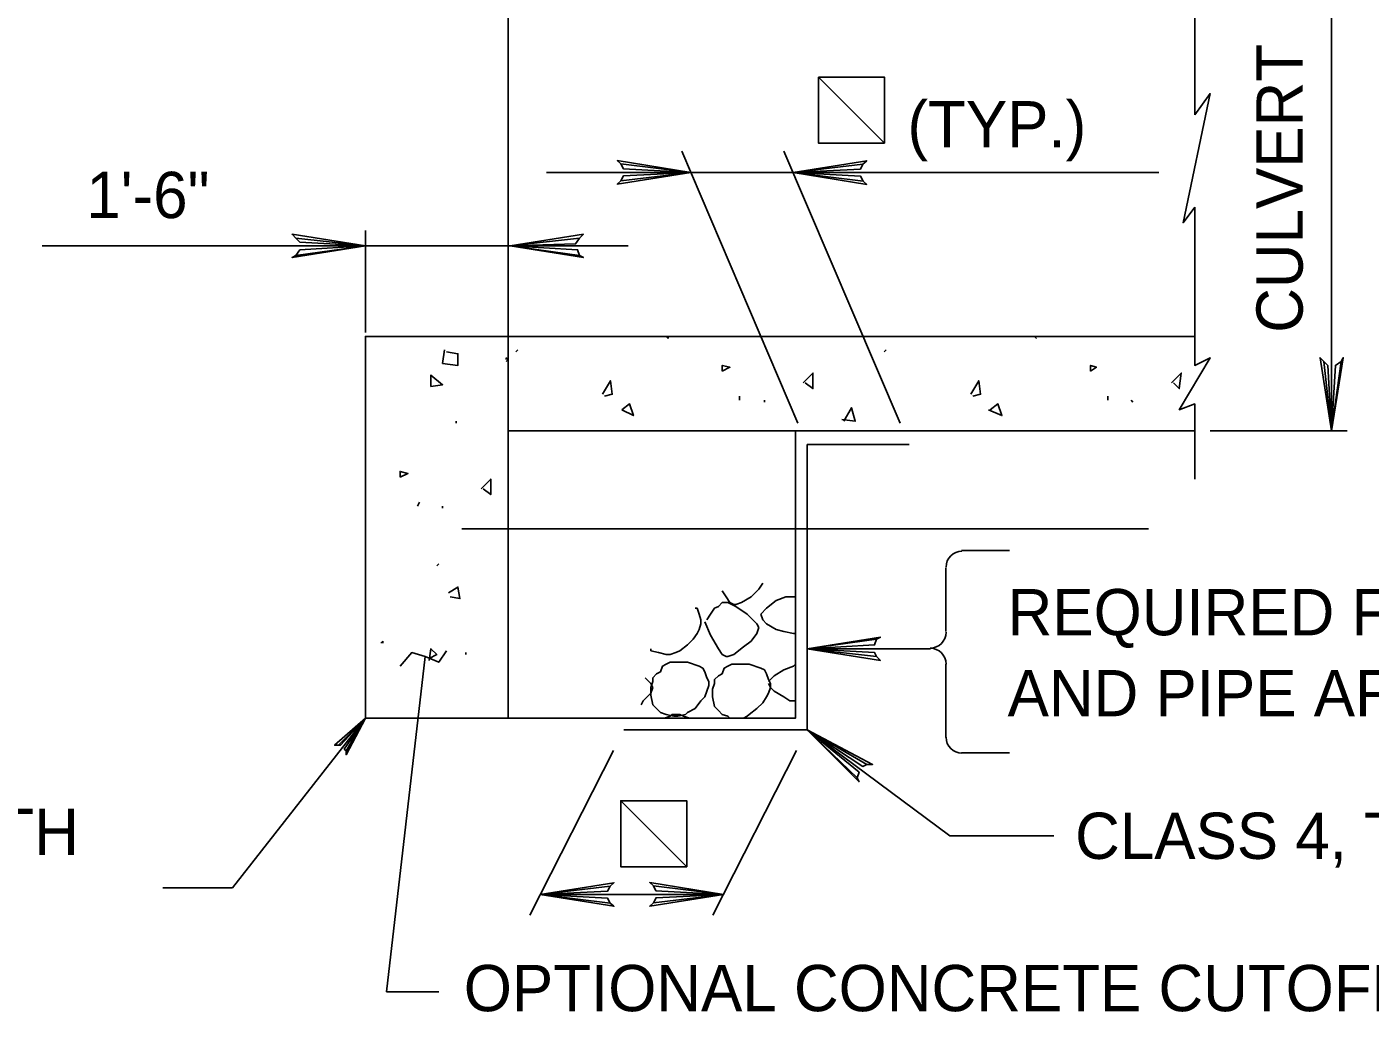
# Model space of a CAD drawing. Extents: x 593 to 1473, y 721 to 1315.
# Drawn here: x 1025.6 to 1112.7, y 1122.4 to 1187.1 of the extents above; entities that cross this region are included whole.
import ezdxf

# ---------------------------------------------------------------- set-up
doc = ezdxf.new("R2010")
doc.units = 0
doc.layers.add('1', color=7, linetype='Continuous')
doc.layers.add('2', color=7, linetype='Continuous')

msp = doc.modelspace()

# ---------------------------------------------------------------- linework, layer by layer
at = {"layer": '1'}
for p, q in [((1081.181, 1179.553), (1076.903, 1183.828)), ((1068.358, 1132.639), (1064.081, 1136.913))]:
    msp.add_line(p, q, dxfattribs=at)
for points in [[(1081.181, 1179.553), (1076.903, 1179.553), (1076.903, 1183.828), (1081.181, 1183.828)], [(1081.181, 1179.553), (1076.903, 1183.828), (1081.181, 1183.828)], [(1068.358, 1132.639), (1064.081, 1132.639), (1064.081, 1136.913), (1068.358, 1136.913)], [(1068.358, 1132.639), (1064.081, 1136.913), (1068.358, 1136.913)]]:
    msp.add_lwpolyline(points, close=True, dxfattribs=at)
for points in [[(1064.085, 1178.223), (1064.254, 1177.894), (1068.626, 1177.653), (1064.085, 1178.223), (1063.852, 1178.422), (1068.626, 1177.653), (1064.258, 1177.437), (1064.098, 1177.111), (1068.626, 1177.653), (1063.852, 1176.894), (1064.098, 1177.111)], [(1064.085, 1178.223), (1064.254, 1177.894), (1068.626, 1177.653), (1064.085, 1178.223), (1063.852, 1178.422), (1068.626, 1177.653), (1064.258, 1177.437), (1064.098, 1177.111), (1068.626, 1177.653), (1063.852, 1176.894), (1064.098, 1177.111)], [(1079.792, 1177.083), (1079.622, 1177.411), (1075.251, 1177.653), (1079.792, 1177.083), (1080.024, 1176.883), (1075.251, 1177.653), (1079.619, 1177.869), (1079.778, 1178.194), (1075.251, 1177.653), (1080.024, 1178.411), (1079.778, 1178.194)], [(1063.401, 1130.272), (1063.232, 1130.601), (1058.861, 1130.842), (1063.401, 1130.272), (1063.634, 1130.073), (1058.861, 1130.842), (1063.228, 1131.058), (1063.388, 1131.383), (1058.861, 1130.842), (1063.634, 1131.601), (1063.388, 1131.383)], [(1063.401, 1130.272), (1063.232, 1130.601), (1058.861, 1130.842), (1063.401, 1130.272), (1063.634, 1130.073), (1058.861, 1130.842), (1063.228, 1131.058), (1063.388, 1131.383), (1058.861, 1130.842), (1063.634, 1131.601), (1063.388, 1131.383)], [(1066.195, 1131.412), (1066.364, 1131.083), (1070.736, 1130.842), (1066.195, 1131.412), (1065.962, 1131.611), (1070.736, 1130.842), (1066.368, 1130.626), (1066.208, 1130.301), (1070.736, 1130.842), (1065.962, 1130.084), (1066.208, 1130.301)]]:
    msp.add_lwpolyline(points, dxfattribs=at)
at = {"layer": '2'}
for p, q in [((1056.783, 1160.896), (1056.783, 1198.021)), ((1110.158, 1160.896), (1110.158, 1198.021)), ((1101.283, 1193.521), (1101.283, 1181.396)), ((1075.569, 1161.4), (1068.036, 1179.032)), ((1082.194, 1161.4), (1074.661, 1179.032)), ((1059.276, 1177.653), (1068.626, 1177.653)), ((1068.626, 1177.653), (1075.251, 1177.653)), ((1075.251, 1177.653), (1098.949, 1177.653)), ((1101.283, 1175.396), (1101.283, 1165.146)), ((1047.533, 1167.271), (1047.533, 1173.896)), ((1056.783, 1168.021), (1056.783, 1173.896)), ((1026.587, 1172.896), (1057.033, 1172.896)), ((1056.908, 1172.896), (1064.555, 1172.896)), ((1056.783, 1167.021), (1101.283, 1167.021)), ((1067.033, 1167.021), (1067.158, 1167.021)), ((1067.158, 1166.896), (1067.033, 1167.021)), ((1067.158, 1167.021), (1067.158, 1166.896)), ((1090.908, 1167.021), (1090.908, 1167.021)), ((1090.908, 1167.021), (1091.033, 1166.896)), ((1091.033, 1166.896), (1090.908, 1167.021)), ((1057.283, 1166.021), (1057.408, 1166.146)), ((1057.408, 1166.146), (1057.283, 1166.021)), ((1057.283, 1166.021), (1057.283, 1166.021)), ((1081.158, 1166.021), (1081.283, 1166.146)), ((1081.283, 1166.146), (1081.158, 1166.021)), ((1081.158, 1166.021), (1081.158, 1166.021)), ((1056.658, 1165.521), (1056.658, 1165.646)), ((1056.658, 1165.646), (1056.783, 1165.521)), ((1056.783, 1165.521), (1056.658, 1165.396)), ((1071.783, 1162.896), (1071.783, 1163.146)), ((1073.408, 1162.771), (1073.408, 1162.896)), ((1095.658, 1162.896), (1095.658, 1163.146)), ((1097.283, 1162.771), (1097.158, 1162.896)), ((1101.283, 1162.646), (1101.283, 1157.771)), ((1053.408, 1161.396), (1053.408, 1161.521)), ((1056.783, 1160.896), (1101.283, 1160.896)), ((1056.783, 1160.896), (1101.283, 1160.896)), ((1075.408, 1142.271), (1075.408, 1160.896)), ((1102.283, 1160.896), (1111.158, 1160.896)), ((1076.158, 1141.521), (1076.158, 1160.021)), ((1076.158, 1160.021), (1082.783, 1160.021)), ((1050.908, 1156.021), (1051.033, 1156.271)), ((1052.533, 1155.896), (1052.533, 1156.021)), ((1053.786, 1154.549), (1098.286, 1154.549)), ((1086.158, 1153.146), (1089.283, 1153.146)), ((1052.158, 1152.146), (1052.283, 1152.271)), ((1085.158, 1147.896), (1085.158, 1152.021)), ((1048.533, 1147.146), (1048.658, 1147.271)), ((1048.658, 1147.271), (1048.658, 1147.146)), ((1076.158, 1146.771), (1084.158, 1146.771)), ((1051.408, 1146.271), (1048.908, 1124.521)), ((1054.033, 1146.396), (1054.033, 1146.521)), ((1085.158, 1141.021), (1085.158, 1145.771)), ((1047.533, 1142.271), (1038.908, 1131.271)), ((1056.783, 1142.271), (1075.408, 1142.271)), ((1064.283, 1141.521), (1076.158, 1141.521)), ((1076.158, 1141.521), (1085.408, 1134.646)), ((1063.604, 1140.184), (1058.181, 1129.505)), ((1075.479, 1140.184), (1070.056, 1129.505)), ((1086.158, 1140.021), (1089.283, 1140.021)), ((1085.408, 1134.646), (1092.158, 1134.646)), ((1034.408, 1131.271), (1038.908, 1131.271)), ((1058.861, 1130.842), (1070.736, 1130.842)), ((1048.908, 1124.521), (1052.283, 1124.521))]:
    msp.add_line(p, q, dxfattribs=at)
for points in [[(1101.283, 1181.396), (1102.283, 1182.771), (1100.533, 1174.396), (1101.283, 1175.396)], [(1043.033, 1173.396), (1043.283, 1173.146), (1047.533, 1172.896), (1043.033, 1173.396), (1042.783, 1173.646), (1047.533, 1172.896), (1043.283, 1172.646), (1043.033, 1172.271), (1047.533, 1172.896), (1042.783, 1172.146), (1043.033, 1172.271)], [(1061.408, 1172.271), (1061.283, 1172.646), (1056.908, 1172.896), (1061.408, 1172.271), (1061.658, 1172.146), (1056.908, 1172.896), (1061.158, 1173.021), (1061.408, 1173.396), (1056.908, 1172.896), (1061.658, 1173.646), (1061.408, 1173.396)], [(1052.658, 1166.146), (1052.533, 1165.271), (1053.533, 1165.146), (1053.533, 1165.896), (1052.783, 1166.021)], [(1070.658, 1164.771), (1070.658, 1165.146), (1071.158, 1165.021), (1070.658, 1164.771)], [(1094.533, 1164.771), (1094.533, 1165.146), (1094.908, 1165.021), (1094.533, 1164.771)], [(1101.283, 1165.146), (1102.283, 1165.646), (1100.283, 1162.271), (1101.283, 1162.646)], [(1110.783, 1165.396), (1110.408, 1165.146), (1110.158, 1160.896), (1110.783, 1165.396), (1110.908, 1165.646), (1110.158, 1160.896), (1109.908, 1165.146), (1109.658, 1165.396), (1110.158, 1160.896), (1109.408, 1165.646), (1109.658, 1165.396)], [(1051.783, 1163.771), (1051.783, 1164.521), (1052.533, 1163.896), (1051.783, 1163.771)], [(1062.908, 1163.271), (1063.408, 1164.146), (1063.533, 1163.271), (1063.033, 1163.146)], [(1075.908, 1164.021), (1076.533, 1164.646), (1076.533, 1163.646), (1076.033, 1164.021)], [(1086.783, 1163.271), (1087.283, 1164.146), (1087.408, 1163.271), (1086.908, 1163.146)], [(1099.783, 1164.021), (1100.408, 1164.646), (1100.283, 1163.646), (1099.908, 1164.021)], [(1064.158, 1162.271), (1064.908, 1161.896), (1064.658, 1162.646), (1064.158, 1162.271)], [(1078.408, 1161.646), (1079.283, 1161.521), (1079.033, 1162.396), (1078.533, 1161.521)], [(1087.908, 1162.271), (1088.783, 1161.896), (1088.533, 1162.646), (1088.033, 1162.271)], [(1049.783, 1157.896), (1049.783, 1158.271), (1050.283, 1158.146), (1049.783, 1157.896)], [(1055.033, 1157.146), (1055.658, 1157.771), (1055.658, 1156.771), (1055.158, 1157.146)], [(1073.283, 1151.021), (1073.033, 1150.646)], [(1052.908, 1150.396), (1053.533, 1150.771), (1053.658, 1150.021), (1053.033, 1150.146)], [(1070.908, 1150.146), (1070.658, 1150.521)], [(1071.158, 1149.771), (1070.908, 1150.146)], [(1072.533, 1150.146), (1071.908, 1149.771)], [(1073.033, 1150.646), (1072.533, 1150.146)], [(1074.158, 1149.896), (1074.783, 1150.146)], [(1074.783, 1150.146), (1075.033, 1150.146)], [(1075.033, 1150.146), (1075.408, 1150.146)], [(1068.908, 1149.396), (1069.033, 1149.396)], [(1069.033, 1149.396), (1069.158, 1149.021)], [(1069.908, 1149.021), (1070.158, 1149.396)], [(1070.158, 1149.396), (1070.408, 1149.521)], [(1070.408, 1149.521), (1070.658, 1149.771)], [(1070.658, 1149.771), (1070.908, 1149.771)], [(1070.908, 1149.771), (1071.033, 1149.771)], [(1071.033, 1149.771), (1071.533, 1149.521)], [(1071.408, 1149.646), (1071.158, 1149.771)], [(1071.533, 1149.646), (1071.408, 1149.646)], [(1071.908, 1149.771), (1071.533, 1149.646)], [(1071.533, 1149.521), (1072.283, 1149.021)], [(1073.158, 1149.021), (1073.533, 1149.396)], [(1073.533, 1149.396), (1074.158, 1149.896)], [(1069.158, 1149.021), (1069.283, 1148.646)], [(1069.283, 1148.396), (1069.158, 1148.021)], [(1069.283, 1148.646), (1069.283, 1148.396)], [(1069.908, 1147.646), (1069.533, 1148.521)], [(1069.658, 1148.646), (1069.908, 1149.021)], [(1072.283, 1149.021), (1072.908, 1148.396)], [(1072.908, 1148.396), (1073.033, 1148.146)], [(1073.283, 1148.646), (1073.158, 1149.021)], [(1073.533, 1148.396), (1073.283, 1148.646)], [(1074.158, 1148.021), (1073.533, 1148.396)], [(1069.033, 1147.771), (1068.783, 1147.396)], [(1069.158, 1148.021), (1069.033, 1147.771)], [(1070.408, 1146.771), (1069.908, 1147.646)], [(1072.908, 1147.771), (1072.533, 1147.271)], [(1073.033, 1148.146), (1072.908, 1147.771)], [(1074.658, 1147.896), (1074.158, 1148.021)], [(1075.283, 1147.771), (1074.658, 1147.896)], [(1075.408, 1147.771), (1075.283, 1147.771)], [(1051.658, 1146.146), (1052.158, 1146.396), (1051.783, 1146.771), (1051.658, 1146.021)], [(1066.033, 1146.646), (1066.033, 1146.771)], [(1068.408, 1147.021), (1067.908, 1146.646)], [(1068.783, 1147.396), (1068.408, 1147.021)], [(1070.658, 1146.396), (1070.408, 1146.771)], [(1072.033, 1146.896), (1071.408, 1146.396)], [(1072.533, 1147.271), (1072.033, 1146.896)], [(1080.658, 1146.271), (1080.533, 1146.521), (1076.158, 1146.771), (1080.658, 1146.271), (1080.908, 1146.021), (1076.158, 1146.771), (1080.533, 1147.021), (1080.658, 1147.396), (1076.158, 1146.771), (1080.908, 1147.521), (1080.658, 1147.396)], [(1049.783, 1145.646), (1050.533, 1146.521), (1051.408, 1146.271), (1052.283, 1145.896), (1052.783, 1146.646)], [(1066.533, 1146.521), (1066.033, 1146.646)], [(1067.033, 1146.396), (1066.533, 1146.521)], [(1067.283, 1146.396), (1067.033, 1146.396)], [(1067.033, 1145.771), (1067.283, 1145.896)], [(1067.658, 1146.521), (1067.283, 1146.396)], [(1067.283, 1145.896), (1067.908, 1145.896)], [(1067.908, 1146.646), (1067.658, 1146.521)], [(1067.908, 1145.896), (1068.408, 1145.896)], [(1068.408, 1145.896), (1069.158, 1145.646)], [(1070.908, 1146.271), (1070.658, 1146.396)], [(1071.033, 1146.271), (1070.908, 1146.271)], [(1071.408, 1146.396), (1071.033, 1146.271)], [(1066.158, 1144.896), (1066.408, 1145.146)], [(1066.408, 1145.146), (1066.658, 1145.271)], [(1066.658, 1145.271), (1066.783, 1145.646)], [(1066.783, 1145.646), (1067.033, 1145.771)], [(1069.158, 1145.646), (1069.408, 1145.521)], [(1069.408, 1145.521), (1069.533, 1145.271)], [(1069.533, 1145.271), (1069.658, 1144.896)], [(1070.158, 1144.771), (1070.408, 1145.021)], [(1070.408, 1145.021), (1070.658, 1145.146)], [(1070.658, 1145.146), (1070.783, 1145.521)], [(1070.783, 1145.521), (1071.033, 1145.646)], [(1071.033, 1145.646), (1071.283, 1145.771)], [(1071.283, 1145.771), (1071.908, 1145.771)], [(1071.908, 1145.771), (1072.408, 1145.771)], [(1072.408, 1145.771), (1073.158, 1145.521)], [(1073.158, 1145.521), (1073.408, 1145.396)], [(1073.408, 1145.396), (1073.533, 1145.146)], [(1073.533, 1145.146), (1073.658, 1144.771)], [(1073.658, 1144.646), (1074.033, 1145.021)], [(1074.033, 1145.021), (1074.658, 1145.396)], [(1074.658, 1145.396), (1075.283, 1145.646)], [(1075.283, 1145.646), (1075.408, 1145.771)], [(1065.658, 1144.896), (1066.033, 1144.521)], [(1066.033, 1144.271), (1066.158, 1144.646)], [(1066.033, 1144.521), (1066.158, 1144.271)], [(1066.033, 1143.771), (1066.033, 1144.271)], [(1066.158, 1144.271), (1066.033, 1143.896)], [(1066.158, 1144.646), (1066.158, 1144.896)], [(1069.658, 1144.896), (1069.783, 1144.646)], [(1069.783, 1144.396), (1069.658, 1144.021)], [(1069.783, 1144.646), (1069.783, 1144.396)], [(1070.033, 1144.146), (1070.158, 1144.521)], [(1070.033, 1143.646), (1070.033, 1144.146)], [(1070.158, 1144.521), (1070.158, 1144.771)], [(1073.658, 1144.771), (1073.783, 1144.521)], [(1073.783, 1144.271), (1073.658, 1144.521)], [(1073.783, 1144.271), (1073.658, 1143.896)], [(1073.783, 1144.521), (1073.783, 1144.271)], [(1074.033, 1144.021), (1073.783, 1144.271)], [(1065.533, 1143.396), (1065.408, 1143.146)], [(1066.033, 1143.896), (1065.533, 1143.396)], [(1066.158, 1143.146), (1066.033, 1143.771)], [(1069.283, 1143.396), (1068.908, 1142.896)], [(1069.533, 1143.646), (1069.283, 1143.396)], [(1069.658, 1144.021), (1069.533, 1143.646)], [(1070.158, 1143.021), (1070.033, 1143.646)], [(1073.283, 1143.271), (1072.908, 1142.896)], [(1073.533, 1143.646), (1073.283, 1143.271)], [(1073.658, 1143.896), (1073.533, 1143.646)], [(1074.658, 1143.646), (1074.033, 1144.021)], [(1075.033, 1143.396), (1074.658, 1143.646)], [(1075.408, 1143.396), (1075.033, 1143.396)], [(1066.408, 1142.896), (1066.158, 1143.146)], [(1066.658, 1142.646), (1066.408, 1142.896)], [(1067.033, 1142.521), (1066.658, 1142.646)], [(1066.908, 1142.271), (1067.283, 1142.396)], [(1067.533, 1142.396), (1067.033, 1142.521)], [(1067.283, 1142.396), (1067.408, 1142.521)], [(1067.408, 1142.521), (1067.908, 1142.521)], [(1067.783, 1142.396), (1067.533, 1142.396)], [(1068.283, 1142.521), (1067.783, 1142.396)], [(1067.908, 1142.521), (1068.158, 1142.396)], [(1068.158, 1142.396), (1068.533, 1142.271)], [(1068.408, 1142.646), (1068.283, 1142.521)], [(1068.908, 1142.896), (1068.408, 1142.646)], [(1070.408, 1142.771), (1070.158, 1143.021)], [(1070.658, 1142.521), (1070.408, 1142.771)], [(1071.033, 1142.396), (1070.658, 1142.521)], [(1071.158, 1142.271), (1071.033, 1142.396)], [(1072.283, 1142.396), (1072.033, 1142.271)], [(1072.408, 1142.521), (1072.283, 1142.396)], [(1072.908, 1142.896), (1072.408, 1142.521)], [(1045.783, 1140.521), (1045.908, 1140.521), (1047.533, 1142.271), (1045.783, 1140.521), (1045.533, 1140.521), (1047.533, 1142.271), (1046.158, 1140.271), (1046.283, 1140.146), (1047.533, 1142.271), (1046.283, 1139.896), (1046.283, 1140.146)], [(1079.408, 1138.396), (1079.533, 1138.771), (1076.158, 1141.521), (1079.408, 1138.396), (1079.533, 1138.146), (1076.158, 1141.521), (1079.783, 1139.146), (1080.033, 1139.271), (1076.158, 1141.521), (1080.408, 1139.271), (1080.033, 1139.271)]]:
    msp.add_lwpolyline(points, dxfattribs=at)
for points in [[(1056.783, 1167.021), (1056.783, 1142.271), (1047.533, 1142.271), (1047.533, 1167.021)], [(1056.783, 1160.896), (1101.283, 1160.896), (1101.283, 1162.646), (1100.283, 1162.271), (1102.283, 1165.646), (1101.283, 1165.146), (1101.283, 1167.021), (1056.783, 1167.021)], [(1056.783, 1142.271), (1056.783, 1160.896), (1075.408, 1160.896), (1075.408, 1142.271)]]:
    msp.add_lwpolyline(points, close=True, dxfattribs=at)
for centre, start, end in [((1086.198, 1152.065), 90, 180), ((1084.135, 1147.842), 270, 0), ((1084.135, 1145.78), 0, 90), ((1086.198, 1141.032), 180, 270)]:
    msp.add_arc(centre, 1.031, start, end, dxfattribs=at)

# ---------------------------------------------------------------- texts
msp.add_text(' CULVERT ', height=3, rotation=90, dxfattribs=at).set_placement((1108.283, 1166.146))
for s, p in [('(TYP.)', (1082.667, 1179.281)), ('1\'-6"', (1029.442, 1174.697)), ('REQUIRED FOR BOX CULVERTS', (1089.158, 1147.646)), ('AND PIPE ARCHES ONLY', (1089.158, 1142.396)), ('BELOW SCOUR DEPTH', (984.158, 1133.396)), ('CLASS 4, TYPE A GEOTEXTILE ', (1093.533, 1133.146)), ('OPTIONAL CONCRETE CUTOFF WALL (CLASS A CEM.CONC.)', (1053.908, 1123.271))]:
    msp.add_text(s, height=3, dxfattribs=at).set_placement(p)

doc.saveas('drawing.dxf')
